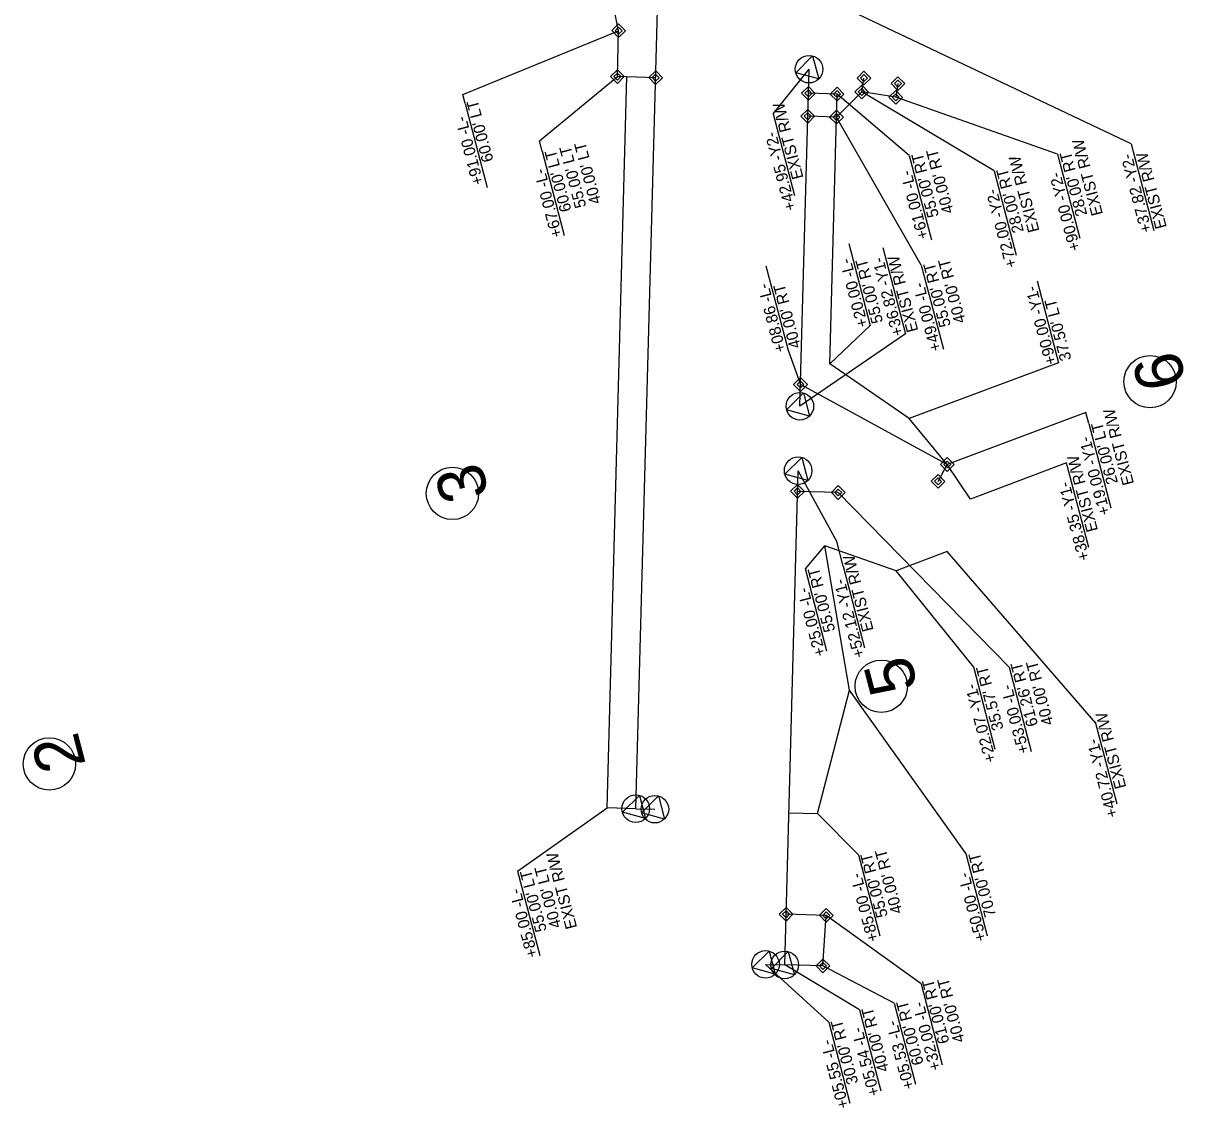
# Model space of a CAD drawing. Extents: x 1366833 to 1368739, y 877580 to 880469.
# Drawn here: x 1367155 to 1367761, y 878792 to 879359 of the extents above; entities that cross this region are included whole.
import ezdxf

# ---------------------------------------------------------------- set-up
doc = ezdxf.new("R2010")
doc.units = 0
for name, color, linetype in [('Exist Hydro Jurisdictional Stream or Body of Water', 7, 'Continuous'), ('Exist Hydrographic River Shore', 7, 'Continuous'), ('Exist Road Primary NC Attributed', 7, 'Continuous'), ('Exist Structure Major Deck Tunnel Box Culvert', 7, 'Continuous'), ('P_NCDOT_Horizontal_Alignment', 7, 'Continuous'), ('P_NCDOT_Vertical_Profile_Grade', 7, 'Continuous'), ('P_RDY_Profile_Special_Ditch_L', 7, 'Continuous'), ('Prop Horizontal Alignment Station Label', 7, 'Continuous'), ('Prop North Arrow for Plan Sheets CELL', 7, 'Continuous'), ('Prop Shade Medium', 7, 'Continuous'), ('Scratch_Level_0', 7, 'Continuous'), ('Scratch_Level_3', 7, 'Continuous'), ('Sheet Clip Boundary CELL', 7, 'Continuous'), ('Sheet Professional Seal CELL', 7, 'Continuous'), ('Sheet Title Data Points CELL', 7, 'Continuous')]:
    doc.layers.add(name, color=color, linetype=linetype)

msp = doc.modelspace()

# ---------------------------------------------------------------- linework, layer by layer
at = {"layer": 'Exist Hydro Jurisdictional Stream or Body of Water'}
for p, q in [((1367617.55, 879289.6), (1367629.09, 879245.59)), ((1367623.82, 879232.36), (1367635.35, 879188.34))]:
    msp.add_line(p, q, dxfattribs=at)
for points in [[(1367617.55, 879289.6), (1367579.82, 879321.64)], [(1367623.82, 879232.36), (1367579.5, 879309.65)]]:
    msp.add_lwpolyline(points, dxfattribs=at)
at = {"layer": 'Exist Hydrographic River Shore'}
for p, q in [((1367474.63, 878948.36), (1367487.43, 879418.66)), ((1367560.38, 879158.57), (1367565.17, 879334.65)), ((1367552.44, 878866.76), (1367559.47, 879124.93)), ((1367474.63, 878948.36), (1367484.63, 878948.09))]:
    msp.add_line(p, q, dxfattribs=at)
at = {"layer": 'Exist Road Primary NC Attributed'}
for p, q in [((1367579.82, 879321.64), (1367564.83, 879322.05)), ((1367579.5, 879309.65), (1367579.82, 879321.64)), ((1367579.5, 879309.65), (1367564.5, 879310.05))]:
    msp.add_line(p, q, dxfattribs=at)
at = {"layer": 'Exist Structure Major Deck Tunnel Box Culvert'}
for p, q in [((1367733.52, 879295.59), (1367566.27, 879374.99)), ((1367546.41, 879311.36), (1367557.58, 879268.73)), ((1367733.52, 879295.59), (1367745.37, 879250.36)), ((1367603.66, 879241.57), (1367615.51, 879196.34)), ((1367579.65, 879087.98), (1367559.47, 879124.93)), ((1367583.04, 879075.07), (1367579.65, 879087.98)), ((1367583.04, 879075.07), (1367594.21, 879032.43)), ((1367412.91, 878915.78), (1367424.48, 878871.65)), ((1367575.47, 878836.82), (1367542.45, 878867.04)), ((1367591.52, 878843.3), (1367552.44, 878866.76)), ((1367591.52, 878843.3), (1367602.62, 878800.95)), ((1367575.47, 878836.82), (1367586.57, 878794.46))]:
    msp.add_line(p, q, dxfattribs=at)
for points in [[(1367546.41, 879311.36), (1367565.17, 879334.65)], [(1367615.51, 879196.34), (1367560.38, 879158.57)], [(1367412.91, 878915.78), (1367459.64, 878948.77)]]:
    msp.add_lwpolyline(points, dxfattribs=at)
at = {"layer": 'P_NCDOT_Horizontal_Alignment'}
msp.add_line((1367542.45, 878867.04), (1367552.44, 878866.76), dxfattribs=at)
at = {"layer": 'P_NCDOT_Vertical_Profile_Grade'}
for p, q in [((1367574.16, 878892.64), (1367553.16, 878893.21)), ((1367572.44, 878866.21), (1367552.44, 878866.76))]:
    msp.add_line(p, q, dxfattribs=at)
at = {"layer": 'P_RDY_Profile_Special_Ditch_L'}
for p, q in [((1367465.68, 879354.76), (1367465.68, 879354.76)), ((1367465.03, 879330.77), (1367465.03, 879330.77)), ((1367485.02, 879330.22), (1367485.02, 879330.22)), ((1367560.69, 879169.96), (1367560.69, 879169.96)), ((1367637.4, 879128.15), (1367637.4, 879128.15)), ((1367632.6, 879119.36), (1367632.6, 879119.36)), ((1367559.17, 879114.13), (1367559.17, 879114.13)), ((1367580.42, 879113.55), (1367580.42, 879113.55))]:
    msp.add_line(p, q, dxfattribs=at)
for points in [[(1367465.7, 879358.36), (1367469.28, 879354.74), (1367465.66, 879351.16), (1367462.08, 879354.78)], [(1367465.69, 879356.56), (1367467.48, 879354.75), (1367465.67, 879352.96), (1367463.88, 879354.77)], [(1367465.05, 879334.37), (1367468.63, 879330.75), (1367465.01, 879327.17), (1367461.43, 879330.79)], [(1367465.04, 879332.57), (1367466.83, 879330.76), (1367465.02, 879328.97), (1367463.23, 879330.78)], [(1367485.04, 879333.82), (1367488.62, 879330.2), (1367485, 879326.62), (1367481.42, 879330.24)], [(1367485.03, 879332.02), (1367486.82, 879330.21), (1367485.01, 879328.42), (1367483.22, 879330.23)], [(1367593.86, 879333.6), (1367597.44, 879329.98), (1367593.82, 879326.4), (1367590.24, 879330.02)], [(1367593.85, 879331.8), (1367595.64, 879329.99), (1367593.83, 879328.2), (1367592.04, 879330.01)], [(1367611.63, 879330.72), (1367615.21, 879327.1), (1367611.59, 879323.52), (1367608.01, 879327.14)], [(1367611.62, 879328.92), (1367613.41, 879327.11), (1367611.6, 879325.32), (1367609.81, 879327.13)], [(1367564.85, 879325.65), (1367568.43, 879322.03), (1367564.81, 879318.45), (1367561.23, 879322.07)], [(1367564.84, 879323.85), (1367566.63, 879322.04), (1367564.82, 879320.25), (1367563.03, 879322.06)], [(1367579.84, 879325.24), (1367583.42, 879321.62), (1367579.8, 879318.04), (1367576.22, 879321.66)], [(1367579.83, 879323.44), (1367581.62, 879321.63), (1367579.81, 879319.84), (1367578.02, 879321.65)], [(1367592.73, 879326.34), (1367596.31, 879322.72), (1367592.69, 879319.14), (1367589.11, 879322.76)], [(1367592.72, 879324.54), (1367594.51, 879322.73), (1367592.7, 879320.94), (1367590.91, 879322.75)], [(1367610.51, 879323.56), (1367614.09, 879319.94), (1367610.47, 879316.36), (1367606.89, 879319.98)], [(1367610.5, 879321.76), (1367612.29, 879319.95), (1367610.48, 879318.16), (1367608.69, 879319.97)], [(1367564.52, 879313.65), (1367568.1, 879310.03), (1367564.48, 879306.46), (1367560.9, 879310.07)], [(1367564.51, 879311.85), (1367566.3, 879310.04), (1367564.49, 879308.25), (1367562.7, 879310.06)], [(1367579.52, 879313.25), (1367583.1, 879309.63), (1367579.48, 879306.05), (1367575.9, 879309.67)], [(1367579.51, 879311.45), (1367581.3, 879309.64), (1367579.49, 879307.85), (1367577.7, 879309.66)], [(1367560.71, 879173.56), (1367564.29, 879169.94), (1367560.67, 879166.37), (1367557.09, 879169.98)], [(1367560.7, 879171.76), (1367562.49, 879169.95), (1367560.68, 879168.16), (1367558.89, 879169.97)], [(1367637.42, 879131.75), (1367641, 879128.13), (1367637.38, 879124.55), (1367633.8, 879128.17)], [(1367637.41, 879129.95), (1367639.2, 879128.14), (1367637.39, 879126.35), (1367635.6, 879128.16)], [(1367632.62, 879122.96), (1367636.2, 879119.34), (1367632.58, 879115.76), (1367629, 879119.38)], [(1367559.19, 879117.73), (1367562.77, 879114.11), (1367559.15, 879110.53), (1367555.57, 879114.15)], [(1367559.18, 879115.93), (1367560.97, 879114.12), (1367559.16, 879112.33), (1367557.37, 879114.14)], [(1367580.44, 879117.15), (1367584.02, 879113.53), (1367580.4, 879109.95), (1367576.82, 879113.57)], [(1367632.61, 879121.16), (1367634.4, 879119.35), (1367632.59, 879117.56), (1367630.8, 879119.37)], [(1367580.43, 879115.35), (1367582.22, 879113.54), (1367580.41, 879111.75), (1367578.62, 879113.56)], [(1367553.18, 878896.81), (1367556.76, 878893.19), (1367553.14, 878889.61), (1367549.56, 878893.23)], [(1367553.17, 878895.01), (1367554.96, 878893.2), (1367553.15, 878891.41), (1367551.36, 878893.22)], [(1367574.18, 878896.24), (1367577.76, 878892.62), (1367574.14, 878889.04), (1367570.56, 878892.66)], [(1367574.17, 878894.44), (1367575.96, 878892.63), (1367574.15, 878890.84), (1367572.36, 878892.65)], [(1367572.46, 878869.8), (1367576.04, 878866.19), (1367572.42, 878862.61), (1367568.84, 878866.22)], [(1367572.45, 878868.01), (1367574.24, 878866.2), (1367572.43, 878864.41), (1367570.64, 878866.22)]]:
    msp.add_lwpolyline(points, close=True, dxfattribs=at)
at = {"layer": 'Prop Horizontal Alignment Station Label'}
for p, q in [((1367384.25, 879321.37), (1367465.68, 879354.76)), ((1367424.37, 879297.23), (1367465.03, 879330.77)), ((1367385.44, 879316.81), (1367384.25, 879321.37)), ((1367385.44, 879316.81), (1367396.98, 879272.79)), ((1367425.78, 879291.86), (1367424.37, 879297.23)), ((1367425.78, 879291.86), (1367437.31, 879247.84))]:
    msp.add_line(p, q, dxfattribs=at)
at = {"layer": 'Prop North Arrow for Plan Sheets CELL'}
for p, q in [((1367465.68, 879354.76), (1367421.64, 879573.94)), ((1367465.03, 879330.77), (1367465.68, 879354.76)), ((1367485.02, 879330.22), (1367465.03, 879330.77))]:
    msp.add_line(p, q, dxfattribs=at)
at = {"layer": 'Prop Shade Medium'}
for p, q in [((1367580.42, 879113.55), (1367559.17, 879114.13)), ((1367572.44, 878866.21), (1367574.16, 878892.64))]:
    msp.add_line(p, q, dxfattribs=at)
for points in [[(1367611.61, 879327.12), (1367610.49, 879319.96), (1367592.71, 879322.74), (1367593.84, 879330)], [(1367632.6, 879119.36), (1367637.4, 879128.15), (1367621.59, 879136.77), (1367584.71, 879156.87), (1367560.69, 879169.96)]]:
    msp.add_lwpolyline(points, dxfattribs=at)
at = {"layer": 'Scratch_Level_0'}
for p, q in [((1367585.91, 879243.68), (1367597.16, 879200.77)), ((1367684.35, 879224.12), (1367695.6, 879181.21)), ((1367699.68, 879129.08), (1367649.61, 879110.12)), ((1367700.04, 879127.72), (1367699.68, 879129.08)), ((1367711.29, 879084.8), (1367700.04, 879127.72)), ((1367563.24, 879073.61), (1367573.41, 879085.73)), ((1367714.99, 878992.98), (1367637.33, 879082.65)), ((1367574.49, 879030.69), (1367563.24, 879073.61)), ((1367651.19, 879022.27), (1367610.63, 879072.62)), ((1367662.44, 878979.35), (1367651.19, 879022.27)), ((1367726.09, 878950.64), (1367714.85, 878993.55)), ((1367590.99, 878924.21), (1367569.6, 878945.78)), ((1367590.99, 878924.21), (1367602.09, 878881.86)), ((1367658.49, 878881.81), (1367647.25, 878924.73))]:
    msp.add_line(p, q, dxfattribs=at)
for points in [[(1367597.16, 879200.77), (1367575.99, 879180.69)], [(1367695.6, 879181.21), (1367617.44, 879152.13)], [(1367647.25, 878924.73), (1367586.36, 879010.35)]]:
    msp.add_lwpolyline(points, dxfattribs=at)
at = {"layer": 'Scratch_Level_3'}
for p, q in [((1367565.17, 879334.65), (1367565.17, 879334.65)), ((1367593.84, 879330), (1367593.84, 879330)), ((1367564.83, 879322.05), (1367564.83, 879322.05)), ((1367592.71, 879322.74), (1367592.71, 879322.74)), ((1367611.61, 879327.12), (1367611.61, 879327.12)), ((1367579.82, 879321.64), (1367579.82, 879321.64)), ((1367610.49, 879319.96), (1367610.49, 879319.96)), ((1367564.5, 879310.05), (1367564.5, 879310.05)), ((1367579.5, 879309.65), (1367579.5, 879309.65)), ((1367560.38, 879158.57), (1367560.38, 879158.57)), ((1367559.47, 879124.93), (1367559.47, 879124.93)), ((1367474.63, 878948.36), (1367474.63, 878948.36)), ((1367484.63, 878948.09), (1367484.63, 878948.09)), ((1367553.16, 878893.21), (1367553.16, 878893.21)), ((1367574.16, 878892.64), (1367574.16, 878892.64)), ((1367542.45, 878867.04), (1367542.45, 878867.04)), ((1367552.44, 878866.76), (1367552.44, 878866.76)), ((1367572.44, 878866.21), (1367572.44, 878866.21))]:
    msp.add_line(p, q, dxfattribs=at)
for points in [[(1367558.19, 879332.82), (1367567.06, 879341.59), (1367570.25, 879329.53)], [(1367553.4, 879156.74), (1367562.28, 879165.51), (1367565.46, 879153.45)], [(1367552.49, 879123.1), (1367561.36, 879131.87), (1367564.55, 879119.81)], [(1367467.66, 878946.54), (1367476.53, 878955.31), (1367479.72, 878943.25)], [(1367477.65, 878946.26), (1367486.53, 878955.04), (1367489.71, 878942.97)], [(1367535.47, 878865.21), (1367544.34, 878873.99), (1367547.53, 878861.92)], [(1367545.47, 878864.93), (1367554.34, 878873.71), (1367557.53, 878861.64)]]:
    msp.add_lwpolyline(points, close=True, dxfattribs=at)
for centre in [(1367565.17, 879334.65), (1367560.38, 879158.57), (1367559.47, 879124.93), (1367474.63, 878948.36), (1367484.63, 878948.09), (1367542.45, 878867.04), (1367552.44, 878866.76)]:
    msp.add_circle(centre, 7.2, dxfattribs=at)
at = {"layer": 'Sheet Clip Boundary CELL'}
for p, q in [((1367695.05, 879290.31), (1367706.59, 879246.3)), ((1367661.92, 879281.57), (1367673.46, 879237.55)), ((1367542.66, 879231.85), (1367554.19, 879187.83)), ((1367709.79, 879155.29), (1367637.4, 879128.15)), ((1367711.3, 879149.53), (1367709.79, 879155.29)), ((1367711.3, 879149.53), (1367722.83, 879105.51)), ((1367669.71, 879022.31), (1367580.42, 879113.55)), ((1367669.71, 879022.31), (1367681.25, 878978.29)), ((1367623.7, 878856.85), (1367574.16, 878892.64)), ((1367609.66, 878846.85), (1367572.44, 878866.21)), ((1367623.7, 878856.85), (1367634.8, 878814.5)), ((1367609.66, 878846.85), (1367620.76, 878804.5))]:
    msp.add_line(p, q, dxfattribs=at)
for points in [[(1367661.92, 879281.57), (1367592.71, 879322.74)], [(1367695.05, 879290.31), (1367610.49, 879319.96)], [(1367554.19, 879187.83), (1367560.69, 879169.96)]]:
    msp.add_lwpolyline(points, dxfattribs=at)
at = {"layer": 'Sheet Professional Seal CELL'}
for p, q in [((1367743.37, 879171.44), (1367743.37, 879171.44)), ((1367378.86, 879113.04), (1367378.86, 879113.04)), ((1367602.92, 879012.32), (1367602.92, 879012.32)), ((1367168.25, 878971.73), (1367168.25, 878971.73))]:
    msp.add_line(p, q, dxfattribs=at)
for centre in [(1367743.37, 879171.44), (1367378.86, 879113.04), (1367602.92, 879012.32), (1367168.25, 878971.73)]:
    msp.add_circle(centre, 13.67, dxfattribs=at)
at = {"layer": 'Sheet Title Data Points CELL'}
for p, q in [((1367459.64, 878948.77), (1367470.03, 879330.63)), ((1367579.5, 879309.65), (1367592.71, 879322.74)), ((1367575.99, 879180.69), (1367579.5, 879309.65)), ((1367617.44, 879152.13), (1367575.99, 879180.69)), ((1367637.4, 879128.15), (1367617.44, 879152.13)), ((1367649.61, 879110.12), (1367637.4, 879128.15)), ((1367474.63, 878948.36), (1367459.64, 878948.77))]:
    msp.add_line(p, q, dxfattribs=at)
for points in [[(1367569.6, 878945.78), (1367586.36, 879010.35), (1367573.41, 879085.73)], [(1367637.33, 879082.65), (1367610.63, 879072.62), (1367573.41, 879085.73)], [(1367554.6, 878946.19), (1367569.6, 878945.78)]]:
    msp.add_lwpolyline(points, dxfattribs=at)

# ---------------------------------------------------------------- texts
at = {"layer": 'Exist Hydro Jurisdictional Stream or Body of Water'}
for s, p in [("40.00' RT", (1367640.81, 879260.03)), ("55.00' RT", (1367633.07, 879258)), ('+61.00 -L-', (1367627.76, 879246.72)), ("55.00' RT", (1367639.33, 879200.76)), ("40.00' RT", (1367647.07, 879202.78)), ('+49.00 -L-', (1367634.38, 879188.09))]:
    msp.add_text(s, height=6, rotation=104.68512, dxfattribs=at).set_placement(p)
at = {"layer": 'Exist Structure Major Deck Tunnel Box Culvert'}
for s, p in [('EXIST R/W', (1367562.32, 879278.01)), ('+42.95 -Y2-', (1367558.49, 879261.59)), ('+37.82 -Y2-', (1367744.41, 879250.11)), ('EXIST R/W', (1367752.14, 879252.14)), ('+36.82 -Y1-', (1367614.54, 879196.09)), ('EXIST R/W', (1367622.28, 879198.12)), ('EXIST R/W', (1367598.95, 879041.71)), ('+52.12 -Y1-', (1367594.39, 879028.07)), ('EXIST R/W', (1367444.05, 878886.36)), ("55.00' LT", (1367428.2, 878884.8)), ("40.00' LT", (1367435.81, 878886.79)), ('+85.00 -L-', (1367423.56, 878871.48)), ("40.00' RT", (1367607, 878811.69)), ("30.00' RT", (1367590.95, 878805.2)), ('+05.54 -L-', (1367602.18, 878799.05)), ('+05.55 -L-', (1367586.13, 878792.57))]:
    msp.add_text(s, height=6, rotation=104.68512, dxfattribs=at).set_placement(p)
at = {"layer": 'Prop Horizontal Alignment Station Label'}
for s, p in [("60.00' LT", (1367400.35, 879286.95)), ('+91.00 -L-', (1367395.21, 879274.98)), ("60.00' LT", (1367441.11, 879260.95)), ("55.00' LT", (1367448.85, 879262.98)), ("40.00' LT", (1367456.59, 879265)), ('+67.00 -L-', (1367436.34, 879247.59))]:
    msp.add_text(s, height=6, rotation=104.68512, dxfattribs=at).set_placement(p)
at = {"layer": 'Scratch_Level_0'}
for s, height, p in [('+20.00 -L-', 6, (1367596.15, 879200.66)), ("55.00' RT", 6, (1367603.89, 879202.69)), ('+90.00 -Y1-', 6, (1367694.59, 879181.1)), ("37.50' LT", 6, (1367702.33, 879183.13)), ('6', 25, (1367762.62, 879170.78)), ('3', 25, (1367398.11, 879112.39)), ('EXIST R/W', 6, (1367716.16, 879093.81)), ('+38.35 -Y1-', 6, (1367711.84, 879078.75)), ("55.00' RT", 6, (1367578.91, 879041.44)), ('+25.00 -L-', 6, (1367573.96, 879028.77)), ('5', 25, (1367622.17, 879011.67)), ("35.57' RT", 6, (1367666.86, 878990.1)), ('+22.07 -Y1-', 6, (1367662.99, 878973.3)), ('EXIST R/W', 6, (1367730.97, 878959.61)), ('2', 25, (1367187.42, 878971.38)), ('+40.72 -Y1-', 6, (1367726.65, 878944.58)), ("55.00' RT", 6, (1367606.41, 878892.31)), ("40.00' RT", 6, (1367614.02, 878894.31)), ("70.00' RT", 6, (1367662.91, 878892.56)), ('+85.00 -L-', 6, (1367601.59, 878879.68)), ('+50.00 -L-', 6, (1367657.96, 878879.89))]:
    msp.add_text(s, height=height, rotation=104.68512, dxfattribs=at).set_placement(p)
at = {"layer": 'Sheet Clip Boundary CELL'}
for s, p in [('EXIST R/W', (1367718.76, 879259)), ('EXIST R/W', (1367685.63, 879250.26)), ("28.00' RT", (1367710.57, 879258.71)), ("28.00' RT", (1367677.44, 879249.97)), ('+90.00 -Y2-', (1367707.07, 879240.52)), ('+72.00 -Y2-', (1367673.94, 879231.78)), ('+08.86 -L-', (1367553.22, 879187.58)), ("40.00' RT", (1367560.96, 879189.61)), ('EXIST R/W', (1367735.01, 879118.21)), ("26.00' LT", (1367726.63, 879118.61)), ('+19.00 -Y1-', (1367722.58, 879102.51)), ("40.00' RT", (1367692.97, 878992.74)), ("61.26' RT", (1367684.87, 878992.1)), ('+53.00 -L-', (1367680.28, 878978.04)), ("61.00' RT", (1367638.63, 878826.42)), ("40.00' RT", (1367646.6, 878827.02)), ("60.00' RT", (1367625.14, 878815.24)), ('+32.00 -L-', (1367634.18, 878812.4)), ('+05.53 -L-', (1367620.32, 878802.6))]:
    msp.add_text(s, height=6, rotation=104.68512, dxfattribs=at).set_placement(p)

doc.saveas('drawing.dxf')
